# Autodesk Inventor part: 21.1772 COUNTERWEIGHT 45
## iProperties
Created: 2007-05
Part Number: 21.1772 COUNTERWEIGHT 45
Document SubType Name: Modeling
Designer: Andy Moles
Material: MiniTec Counter Weight Lead
Mass: 3293.54 g
Surface Area: 551.657 cm^2
Volume: 313.67 cm^3
Density: 10.513 g/cm^3
Author: Andy Moles
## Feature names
1. Extrusion1
